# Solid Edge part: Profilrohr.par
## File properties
Username: bmolnar
Dokumentum tartalom típus: 0
Author: bmolnar
Last saved by: bmolnar
Revision: 83
Sűrűség: 0,000 kg/m^3
Pontosság: 0,990
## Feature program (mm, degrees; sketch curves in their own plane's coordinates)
base feature "unnamed BaseFeature 1"
thread "unnamed Thread 1"
thread "Menet_2"  ThreadDepth = 5.5 mm
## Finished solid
Body 1: solid body, 127 faces, 307 edges, 198 vertices.
  Faces by surface: cylinder 57, plane 52, cone 16, torus 2
  Edges by curve: line 144, circle 142, spline 9, curve on surface 7, intersection 5
Bounding box of the edges (mm; curved faces can reach further): 30.000 x 34.000 x 68.000, from (-15, -15, 0) to (15, 19, 68).
Cylindrical faces by radius (mm): R0.3 x24, R0.65 x2, R1.85 x4, R2 x2, R2.067 x4, R2.35 x2, R2.8 x4, R3.75 x4, R8 x1, R8.95 x2, R9.1 x2, R9.5 x2, R20 x4
Conical faces (half-angle, radius in mm at the cone's reference point): 45 deg R2.317 x2, 45 deg R2.95 x4, 45 deg R3.9 x4, 45 deg R8.4 x2, 45 deg R9.2 x2, 45 deg R9.25 x2
Toroidal faces (ring radius, tube radius in mm): R9.4 r0.1 x2
Planar faces by outward normal: +x 6, +y 9, +z 9, -x 6, -y 5, -z 9, oblique 8
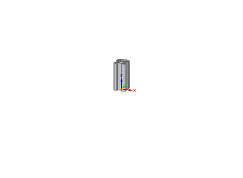
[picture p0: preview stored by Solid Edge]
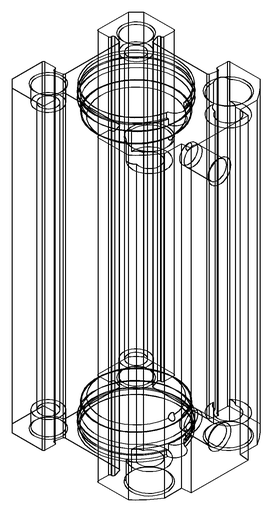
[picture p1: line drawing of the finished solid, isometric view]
